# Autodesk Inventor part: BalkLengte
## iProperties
Created: 2010-03
Part Number: BalkLengte
Document SubType Name: Modeling
Designer: Ferry
Density: 1 g/cm^3
Author: Ferry
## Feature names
1. Extrusion1
